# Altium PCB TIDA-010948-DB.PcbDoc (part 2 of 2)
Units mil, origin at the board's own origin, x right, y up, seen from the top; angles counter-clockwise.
Board outline 8000 x 3300 mil, 4 copper layers (Top Layer, Mid-Layer 1, Mid-Layer 2, Bottom Layer), stack 61.2 mil thick; 16 components, 34 nets, 141 pads, 139 vias.
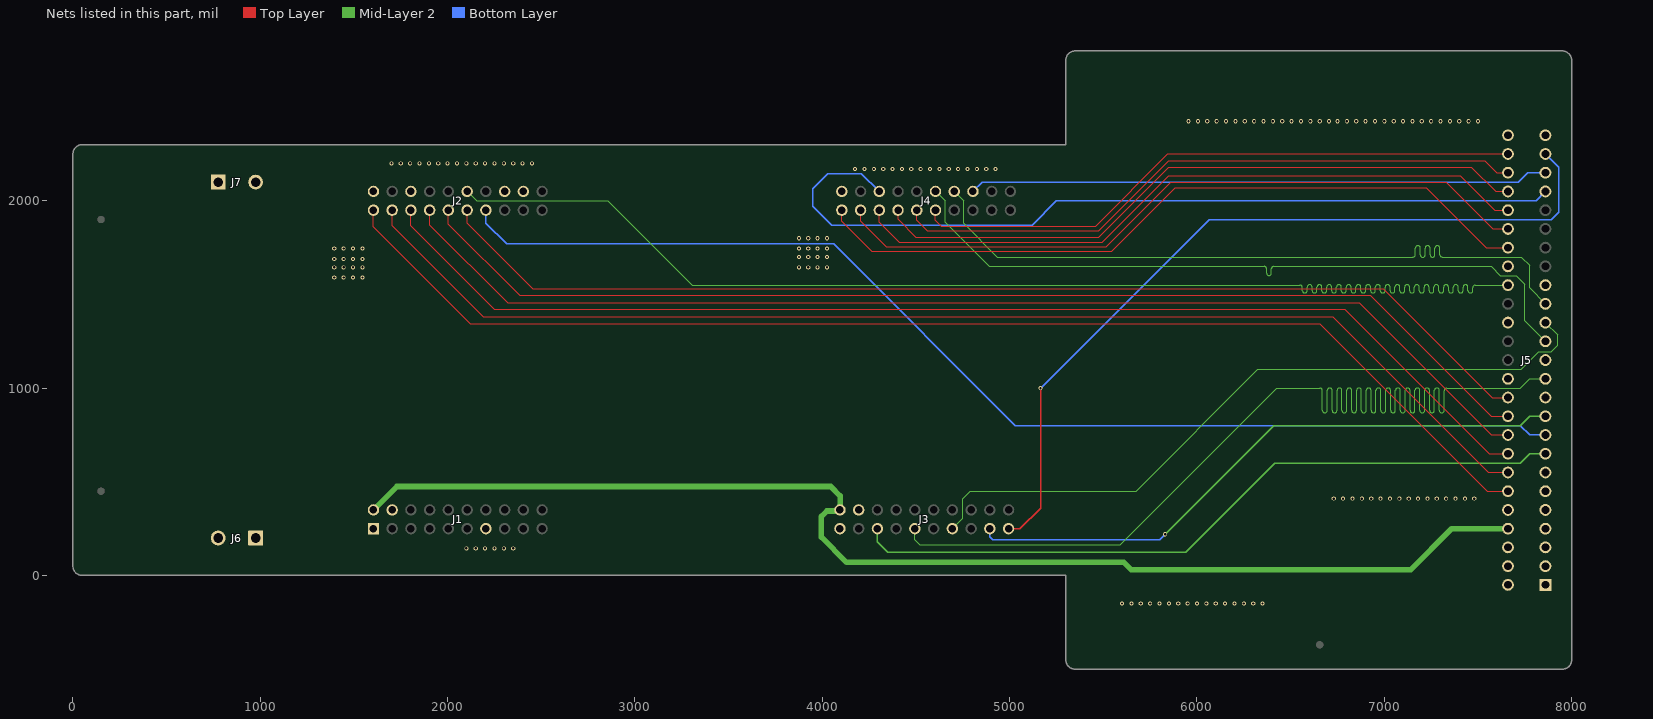
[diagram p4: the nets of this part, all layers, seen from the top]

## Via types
v1: diameter 22, hole 12, Top Layer to Bottom Layer, tented both sides, 136 vias
v2: diameter 200, hole 144, Top Layer to Bottom Layer, 2 vias
v3: diameter 22, hole 8, Top Layer to Bottom Layer, tented both sides, 1 vias

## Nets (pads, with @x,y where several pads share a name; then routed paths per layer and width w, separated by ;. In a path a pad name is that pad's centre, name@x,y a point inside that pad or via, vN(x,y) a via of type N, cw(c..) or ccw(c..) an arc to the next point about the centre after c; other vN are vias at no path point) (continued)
DOUT1_B2: J2.15 J5.51 | length 6942.2
  Mid-Layer 2 w6: J2.15@2104.18,2050 2154.18,2000 2855,2000 3305,1550 6520.53,1550 6549.53,1550 cw(c6549.53,1537) 6562.53,1537 6562.53,1521.18 ccw(c6575.53,1521.18) 6588.53,1521.18 6588.53,1539.22 cw(c6601.53,1539.22) 6614.53,1539.22 6614.53,1521.18 ccw(c6627.53,1521.18) 6640.53,1521.18 6640.53,1539.22 cw(c6653.53,1539.22) 6666.53,1539.22 6666.53,1521.18 ccw(c6679.53,1521.18) 6692.53,1521.18 6692.53,1539.22 cw(c6705.53,1539.22) 6718.53,1539.22 6718.53,1521.18 ccw(c6731.53,1521.18) 6744.53,1521.18 6744.53,1539.22 cw(c6757.53,1539.22) 6770.53,1539.22 6770.53,1521.18 ccw(c6783.53,1521.18) 6796.53,1521.18 6796.53,1539.22 cw(c6809.53,1539.22) 6822.53,1539.22 6822.53,1521.18 ccw(c6835.53,1521.18) 6848.53,1521.18 6848.53,1539.22 cw(c6861.53,1539.22) 6874.53,1539.22 6874.53,1521.18 ccw(c6887.53,1521.18) 6900.53,1521.18 6900.53,1539.22 cw(c6913.53,1539.22) 6926.53,1539.22 6926.53,1521.18 ccw(c6939.53,1521.18) 6952.53,1521.18 6952.53,1539.22 cw(c6965.53,1539.22) 6978.53,1539.22 6978.53,1521.18 ccw(c6991.53,1521.18) 7004.53,1521.18 7004.53,1539.22 cw(c7017.53,1539.22) 7030.53,1539.22 7030.53,1521.18 ccw(c7043.53,1521.18) 7056.53,1521.18 7056.53,1539.22 cw(c7069.53,1539.22) 7082.53,1539.22 7082.53,1521.18 ccw(c7095.53,1521.18) 7108.53,1521.18 7108.53,1539.22 cw(c7121.53,1539.22) 7134.53,1539.22 7134.53,1521.18 ccw(c7147.53,1521.18) 7160.53,1521.18 7160.53,1539.22 cw(c7173.53,1539.22) 7186.53,1539.22 7186.53,1521.18 ccw(c7199.53,1521.18) 7212.53,1521.18 7212.53,1539.22 cw(c7225.53,1539.22) 7238.53,1539.22 7238.53,1521.18 ccw(c7251.53,1521.18) 7264.53,1521.18 7264.53,1539.22 cw(c7277.53,1539.22) 7290.53,1539.22 7290.53,1521.18 ccw(c7303.53,1521.18) 7316.53,1521.18 7316.53,1539.22 cw(c7329.53,1539.22) 7342.53,1539.22 7342.53,1521.18 ccw(c7355.53,1521.18) 7368.53,1521.18 7368.53,1539.22 cw(c7381.53,1539.22) 7394.53,1539.22 7394.53,1521.18 ccw(c7407.53,1521.18) 7420.53,1521.18 7420.53,1539.22 cw(c7433.53,1539.22) 7446.53,1539.22 7446.53,1521.18 ccw(c7459.53,1521.18) 7472.53,1521.18 7472.53,1537 cw(c7485.53,1537) 7485.53,1550 7506.12,1550 J5.51@7660,1550
DOUT1_C1: J2.13
DOUT1_C2: J2.12
DRV_CS: J4.58 J5.64 | length 4547.6
  Bottom Layer w8: J4.58@4304.18,2050 4209.18,2145 4030,2145 3950,2065 3950,1970 4050,1870 5120,1870 5250,2000 7810,2000 J5.64@7860,2050
DRV_FAULT_1: J2.34 J5.25 | length 6193.4
  Bottom Layer w8: J2.34@2204.18,1950 2204.18,1880.82 2315,1770 4060,1770 5030,800 7725,800 7775,750 J5.25@7860,750
DRV_FAULT_2: J4.53 J5.67 | length 3097.2
  Bottom Layer w8: J4.53@4804.18,2050 4854.18,2100 7715,2100 7765,2150 J5.67@7860,2150
DRV_OFF1: J3.49 J5.28 | length 3295.9
  Top Layer w8: J3.49@4894.19,250 J3.49@4896.3,247.89
  Mid-Layer 2 w8: v1(5830,220) 6410,800 7725,800 7775,850 J5.28@7860,850
  Bottom Layer w8: J3.49@4896.3,247.89 J3.49@4894.19,250 4894.19,205.81 4910,190 5800,190 v1(5830,220)
DRV_OFF2: J3.50 J5.70 | length 4356.8
  Top Layer w8: J3.50@4994.19,250 5055,250 5165,360 v1(5165,1000)
  Bottom Layer w8: J3.50@4994.19,250 J3.50@4999.19,245 ; v1(5165,1000) 6065,1900 7890,1900 7930,1940 7930,2180 J5.70@7860,2250
DRV_SPI_CLK: J3.47 J5.43 | length 3844.7
  Mid-Layer 2 w6: J3.47@4694.19,250 4750,305.81 4750,410 4790,450 5675,450 6325,1100 7730,1100 7825,1195 7890,1195 7925,1230 7925,1285 J5.43@7860,1350
DRV_SPI_D0: J4.55 J5.40 | length 3844.1
  Mid-Layer 2 w6: J4.55@4604.18,2050 4605,2050 4655,2000 4655,1885 4890,1650 6329.42,1650 6358.42,1650 cw(c6358.42,1637) 6371.42,1637 6371.42,1614.16 ccw(c6384.42,1614.16) 6397.42,1614.16 6397.42,1637 cw(c6410.42,1637) 6410.42,1650 6475,1650 7570,1650 7620,1600 7705,1600 7750,1555 7750,1360 J5.40@7860,1250
DRV_SPI_D1: J4.54 J5.46 | length 3844.8
  Mid-Layer 2 w6: J4.54@4704.18,2050 4755,1999.18 4755,1880 4935,1700 7150,1700 7153,1700 ccw(c7153,1713) 7166,1713 7166,1747.29 cw(c7179,1747.29) 7192,1747.29 7192,1711.62 ccw(c7205,1711.62) 7218,1711.62 7218,1747.29 cw(c7231,1747.29) 7244,1747.29 7244,1711.62 ccw(c7257,1711.62) 7270,1711.62 7270,1747.29 cw(c7283,1747.29) 7296,1747.29 7296,1713 ccw(c7309,1713) 7309,1700 7355.03,1700 7730,1700 7775,1655 7775,1535 J5.46@7860,1450
DRV_SPI_MUX_S: J3.43 J5.22 | length 3875.6
  Mid-Layer 2 w8: J3.43@4294.19,250 4294.19,180.81 4350,125 5940,125 6415,600 7725,600 7775,650 J5.22@7860,650
GND: J1.22 J2.20 J3.62 J4.60 J5.7 J5.9 J5.15 J5.16 J5.19 J5.31 J5.36 J5.37 J5.45 J5.49 J5.54 J5.73 J5.75 J6.2 J7.2
  other v1: 5600,-150 5650,-150 5700,-150 5750,-150 5800,-150 5850,-150 5900,-150 5950,-150 6000,-150 6050,-150 6100,-150 6150,-150 6200,-150 6250,-150 6300,-150 6350,-150 2100,145 2150,145 2200,145 2250,145 2300,145 2350,145 6730,410 6780,410 6830,410 6880,410 6930,410 6980,410 7030,410 7080,410 7130,410 7180,410 7230,410 7280,410 7330,410 7380,410 7430,410 7480,410 1395,1590 1445,1590 1495,1590 1545,1590 1395,1645 1445,1645 1495,1645 1545,1645 3875,1645 3925,1645 3975,1645 4025,1645 1395,1690 1445,1690 1495,1690 1545,1690 3875,1700 3925,1700 3975,1700 4025,1700 1395,1745 1445,1745 1495,1745 1545,1745 3875,1745 3925,1745 3975,1745 4025,1745 3875,1800 3925,1800 3975,1800 4025,1800 4175,2170 4225,2170 4275,2170 4325,2170 4375,2170 4425,2170 4475,2170 4525,2170 4575,2170 4625,2170 4675,2170 4725,2170 4775,2170 4825,2170 4875,2170 4925,2170 1700,2200 1750,2200 1800,2200 1850,2200 1900,2200 1950,2200 2000,2200 2050,2200 2100,2200 2150,2200 2200,2200 2250,2200 2300,2200 2350,2200 2400,2200 2450,2200 5955,2425 6005,2425 6055,2425 6105,2425 6155,2425 6205,2425 6255,2425 6305,2425 6355,2425 6405,2425 6455,2425 6505,2425 6555,2425 6605,2425 6655,2425 6705,2425 6750,2425 6800,2425 6850,2425 6900,2425 6950,2425 7000,2425 7050,2425 7100,2425 7150,2425 7200,2425 7250,2425 7300,2425 7350,2425 7400,2425 7450,2425 7500,2425
PWM_A1_H: J2.40 J5.18 | length 6729.4
  Top Layer w6: J2.40@1604.18,1950 1604.18,1860.82 2120,1345 6655,1345 7550,450 J5.18@7660,450
PWM_A1_L: J2.39 J5.21 | length 6585
  Top Layer w6: J2.39@1704.18,1950 1704.18,1865.82 2190,1380 6725,1380 7555,550 J5.21@7660,550
PWM_A2_H: J4.77 J5.66 | length 3555.8
  Top Layer w6: J4.77@4405.51,1948.66 J4.77@4404.18,1950 4404.18,1900.82 4500,1805 5475,1805 5850,2180 7465,2180 7595,2050 J5.66@7660,2050
PWM_A2_L: J4.78 J5.63 | length 3687.5
  Top Layer w6: J4.78@4304.18,1950 4304.18,1885.82 4410,1780 5495,1780 5850,2135 7405,2135 7590,1950 J5.63@7660,1950
PWM_B1_H: J2.38 J5.24 | length 6443.6
  Top Layer w6: J2.38@1804.18,1950 1804.18,1865.82 2250,1420 6790,1420 7560,650 J5.24@7660,650
PWM_B1_L: J2.37 J5.27 | length 6299.3
  Top Layer w6: J2.37@1904.18,1950 1904.18,1870.82 2320,1455 6865,1455 7570,750 J5.27@7660,750
PWM_B2_H: J4.75 J5.72 | length 3282.2
  Top Layer w6: J4.75@4604.18,1950 4604.18,1895.82 4635,1865 5460,1865 5845,2250 J5.72@7660,2250
PWM_B2_L: J4.76 J5.69 | length 3417.5
  Top Layer w6: J4.76@4504.18,1950 4504.18,1895.82 4560,1840 5475,1840 5850,2215 7535,2215 7600,2150 J5.69@7660,2150 J5.69@7658.5,2151.5
PWM_C1_H: J2.36 J5.30 | length 6154.9
  Top Layer w6: J2.36@2004.18,1950 2004.18,1875.82 2385,1495 6925,1495 7570,850 J5.30@7660,850
PWM_C1_L: J2.35 J5.33 | length 6010.6
  Top Layer w6: J2.35@2104.18,1950 2104.18,1880.82 2455,1530 6995,1530 7575,950 J5.33@7660,950
PWM_C2_H: J4.79 J5.60 | length 3817.7
  Top Layer w6: J4.79@4204.18,1950 4204.18,1890.82 4340,1755 5515,1755 5860,2100 7330,2100 7580,1850 J5.60@7660,1850
PWM_C2_L: J4.80 J5.57 | length 3955
  Top Layer w6: J4.80@4104.18,1950 4104.18,1890.82 4265,1730 5545,1730 5885,2070 7225,2070 7545,1750 J5.57@7660,1750
SDFM_CLK_IN: J1.7
SDFM_CLK_SHIFT: J2.18
SDFM_CLK_SOURCE_BUF: J3.45 J5.34 | length 6948.4
  Mid-Layer 2 w6: J3.45@4494.19,250 4494.19,190.81 4520,165 5590,165 6425,1000 6634.54,1000 6656.45,1000 cw(c6656.45,987) 6669.45,987 6669.45,881.38 ccw(c6682.45,881.38) 6695.45,881.38 6695.45,987.59 cw(c6708.45,987.59) 6721.45,987.59 6721.45,881.38 ccw(c6734.45,881.38) 6747.45,881.38 6747.45,987.59 cw(c6760.45,987.59) 6773.45,987.59 6773.45,881.38 ccw(c6786.45,881.38) 6799.45,881.38 6799.45,987.59 cw(c6812.45,987.59) 6825.45,987.59 6825.45,881.38 ccw(c6838.45,881.38) 6851.45,881.38 6851.45,987.59 cw(c6864.45,987.59) 6877.45,987.59 6877.45,881.38 ccw(c6890.45,881.38) 6903.45,881.38 6903.45,987.59 cw(c6916.45,987.59) 6929.45,987.59 6929.45,881.38 ccw(c6942.45,881.38) 6955.45,881.38 6955.45,987.59 cw(c6968.45,987.59) 6981.45,987.59 6981.45,881.38 ccw(c6994.45,881.38) 7007.45,881.38 7007.45,987.59 cw(c7020.45,987.59) 7033.45,987.59 7033.45,881.38 ccw(c7046.45,881.38) 7059.45,881.38 7059.45,987.59 cw(c7072.45,987.59) 7085.45,987.59 7085.45,881.38 ccw(c7098.45,881.38) 7111.45,881.38 7111.45,987.59 cw(c7124.45,987.59) 7137.45,987.59 7137.45,881.38 ccw(c7150.45,881.38) 7163.45,881.38 7163.45,987.59 cw(c7176.45,987.59) 7189.45,987.59 7189.45,881.38 ccw(c7202.45,881.38) 7215.45,881.38 7215.45,987.59 cw(c7228.45,987.59) 7241.45,987.59 7241.45,881.38 ccw(c7254.45,881.38) 7267.45,881.38 7267.45,987.59 cw(c7280.45,987.59) 7293.45,987.59 7293.45,881.38 ccw(c7306.45,881.38) 7319.45,881.38 7319.45,987 cw(c7332.45,987) 7332.45,1000 7335.45,1000 7725,1000 7775,1050 J5.34@7860,1050
VBus: J5.1 J5.3 J5.4 J5.6 J6.1 J7.1
VSYS_3V3: J1.1 J3.41 J5.10 J5.13
VSYS_5V0: J1.21 J3.61 J5.12 | length 6690.9
  Mid-Layer 2 w30: J1.21@1604.18,350 1729.18,475 4045,475 4095,425 4095,350.81 J3.61@4094.19,350 4088.25,344.06 4024.06,344.06 3995,315 3995,205 4130,70 5610,70 5650,30 7140,30 7360,250 J5.12@7660,250
pads on no net: FID1.1 FID2.1 FID3.1 FID4.1 FID5.1 FID6.1 J1.2 J1.3 J1.4 J1.5 J1.6 J1.8 J1.9 J1.10 J1.23 J1.24 J1.25 J1.26 J1.27 J1.28 J1.29 J1.30 J2.11 J2.14 J2.16 J2.17 J2.31 J2.33 J3.42 J3.46 J3.48 J3.63 J3.64 J3.65 J3.66 J3.67 J3.68 J3.69 J3.70 J4.51 J4.52 J4.56 J4.57 J4.59 J4.71 J4.72 J4.73 J4.74 J5.52 J5.55 J5.58 J5.61 LBL1.0
copper on no net:
  other v2: 154.17,150 154.17,2150

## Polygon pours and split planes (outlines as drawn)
VBus on Bottom Layer "VBUS_L04_P012" (solid, pour order 12): 1075,500 1065,490 1065,500
VBus on Bottom Layer " " (solid, pour order 0): 7905,-125 6425,-125 5800,500 1065,500 1065,75 675,75 650,100 650,2200 675,2225 850,2225 875,2200 875,675 925,625 5905,625 6480,50 7525,50 7580,105 7895,105 7950,50 7950,-80
GND on Bottom Layer "GND_L04_P006" (solid, pour order 6): 650,2200 700,2250 5300,2250 5575,2525 7875,2525 7950,2450 7950,-80 7830,-200 5575,-200 5375,0 5300,75 730,75 650,155
GND on Mid-Layer 1 "GND_L02_P008" (solid, pour order 8): 645,2195 695,2245 5295,2245 5570,2520 7870,2520 7965,2425 7965,-65 7825,-205 5570,-205 5370,-5 5295,70 725,70 645,150
VSYS_3V3 on Mid-Layer 1 "VSYS_3V3_L02_P003" (solid, pour order 3): 7915,95 7895,75 7475,75 1550,75 1475,150 1475,250 1525,300 7690,300 7790,400 7900,400 7915,385
GND on Top Layer "GND_L01_P001" (solid, pour order 1): 645,2195 695,2245 5295,2245 5570,2520 7870,2520 7945,2445 7945,-85 7825,-205 5570,-205 5370,-5 5295,70 725,70 645,150
GND on Mid-Layer 2 "GND_L03_P009" (solid, pour order 9): 645,2195 695,2245 5295,2245 5570,2520 7870,2520 7945,2445 7945,-85 7825,-205 5570,-205 5370,-5 5295,70 725,70 645,150

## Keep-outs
Keep-Out Layer:
  lines w10: 4550,2905 cw(c4550,2900) 4555,2900 ccw(c4550,2900) 4550,2905
  text ".Layer_Name" at 177,-1408.49 h60

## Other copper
Top Layer:
  text ".Layer_Name" at 177,-1408.49 h60
Mid-Layer 1:
Bottom Layer:
  pour cut-out: 1075.2,489.8 1100.2,489.8 1075.2,464.8
  pour cut-out: 1075.2,75 1075.2,100 1100.2,75
  pour cut-out: 1065,75 1040,75 1065,100
  text ".Layer_Name" at 177,-1408.49 h60

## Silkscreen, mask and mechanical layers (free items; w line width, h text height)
Top Overlay:
  text "3V3" at 1630,35 h35 r90
  text ".Layer_Name" at 177,-1408.49 h60
Bottom Overlay:
  text "GND" at 1618,2228 h40 r90
  text "VBUS" at 790,1820 h35 r90
  text "GND" at 1010,1820 h35 r90
  text "TIDA-010948" at 3758.98,885 h60
  text "Rev.E1" at 3085,875.81 h80
  text "TI" at 2454,875 h60
  text ".CopyrightYear" at 2730,875 h60
  text "©" at 2830,870 h105
  text "GND" at 795,640 h35 r90
  text "VBUS" at 995,640 h35 r90
  text ".Layer_Name" at 177,-1408.49 h60
Top Paste:
  text ".Layer_Name" at 177,-1408.49 h60
Bottom Paste:
  text ".Layer_Name" at 177,-1408.49 h60
Top Solder:
  text ".Layer_Name" at 177,-1408.49 h60
  text ".Layer_Name" at 177,-1408.49 h60
Bottom Solder:
  text ".Layer_Name" at 177,-1408.49 h60
Drill Guide:
  text ".Layer_Name" at 177,-1408.49 h60
M1 Board Outline:
  the board outline again, w10
  text ".Layer_Name" at 177,-1408.49 h60
M2 Board Dimensions:
  rectangle: -400,-825 -275,-700
  rectangle: -275,-950 100,-825
  lines w7: -400,-825 600,-825 ; -275,-950 -275,-700 ; -150,-950 -150,-700 ; 100,-950 100,-700 ; 350,-950 350,-700 ; -400,-950 600,-950 600,-700 -400,-700 -400,-950
  text ".Layer_Name" at 177,-1408.49 h60
M3 3D STEP Top:
  text ".Layer_Name" at 177,-1408.49 h60
M4 3D STEP Bottom:
  text ".Layer_Name" at 177,-1408.49 h60
M5 Assembly Top:
  lines w10: -692,-1480.17 5908,-1480.17 ; -692,-1276.83 5910,-1276.83 ; -692,-1073.5 -692,-1683.5 3313,-1683.5 5910,-1683.5 5910,-1073.5 -691.5,-1073.5 -691.5,-1683.5 884,-1683.5 ; 1773,-1683.5 1773,-1073.5 ; 3040,-1276.83 3040,-1073.5 ; 3880,-1276.83 3880,-1073.5 ; 4502,-1690 4502,-1487.17
  text "COMPONENTS MARKED 'DNP' SHOULD NOT BE POPULATED." at 753.5,-868.5 h60
  text "ASSEMBLY VARIANT:" at 753,-984 h60
  text ".VariantName" at 1789,-984 h60
  text "PCB VIEWED FROM TOP SIDE" at -628.5,-1205.67 h60
  text "BOARD #:" at 1848,-1205.67 h60
  text ".PRJ_Number" at 2393.5,-1205.67 h60
  text "REV:" at 3238,-1205.67 h60
  text ".PCB_Rev" at 3529.5,-1205.67 h60
  text "SVN REV:" at 4076,-1205.67 h60
  text ".VersionControl_RevNumber" at 4582,-1205.67 h60
  text "PLOT NAME =" at -628.5,-1614.34 h60
  text ".plot_File_Name" at 177,-1614.34 h60
  text "GENERATED    :" at 1850,-1614.34 h60
  text ".Print_Date" at 2719.5,-1614.34 h60
  text ".Print_Time" at 3448.5,-1614.34 h60
  text "TEXAS INSTRUMENTS" at 4713,-1614.34 h60
M6 Assembly Bottom:
  lines w10: -692.5,-1277.33 5909.5,-1277.33 ; -690.5,-1480.67 5909.5,-1480.67 ; 715.5,-1690.5 715.5,-1487.67 ; 1337.5,-1277.33 1337.5,-1074 ; 2177.5,-1277.33 2177.5,-1074 ; 3444.5,-1684 3444.5,-1074 ; 4333.5,-1684 5909,-1684 5909,-1074 -692.5,-1074 -692.5,-1684 1904.5,-1684 5909.5,-1684 5909.5,-1074
  text "COMPONENTS MARKED 'DNP' SHOULD NOT BE POPULATED." at 5702,-868 h60
  text ".VariantName" at 4658,-984 h60
  text "ASSEMBLY VARIANT:" at 5697,-984 h60
  text ".VersionControl_RevNumber" at 635.5,-1206.17 h60
  text "SVN REV:" at 1141.5,-1206.17 h60
  text ".PCB_Rev" at 1688,-1206.17 h60
  text "REV:" at 1979.5,-1206.17 h60
  text ".PRJ_Number" at 2824,-1206.17 h60
  text "BOARD #:" at 3369.5,-1206.17 h60
  text "PCB VIEWED FROM BOTTOM SIDE" at 5846,-1206.17 h60
  text "TEXAS INSTRUMENTS" at 504.5,-1614.84 h60
  text ".Print_Time" at 1769,-1614.84 h60
  text ".Print_Date" at 2498,-1614.84 h60
  text "GENERATED    :" at 3367.5,-1614.84 h60
  text ".plot_File_Name" at 5040.5,-1614.84 h60
  text "PLOT NAME =" at 5846,-1614.84 h60
M9 Title Sheet:
  drawing of 57 lines, arcs and shapes, not listed
  text "1" at 339.84,7486.5 h70
  text "2" at 2835.5,7486.5 h70
  text "3" at 5324.84,7486.5 h70
  text "4" at 7831.51,7486.5 h70
  text "5" at 10330.5,7486.5 h70
  text "6" at 12835.5,7486.5 h70
  text "A" at -816.5,6343.5 h70
  text "A" at 13983.5,6343.5 h70
  text "B" at -816.5,3963.5 h70
  text "B" at 13983.5,3963.5 h70
  text "C" at -816.5,1588.5 h70
  text "C" at 13983.5,1588.5 h70
  text "PROJECT TITLE:" at 10943.5,-272.5 h45
  text ".PRJ_Title" at 10993.5,-405.83 h70
  text "DESIGNED FOR:" at 10943.5,-573.5 h45
  text ".PRJ_Customer" at 10993.5,-713.5 h70
  text "D" at -816.5,-781.5 h70
  text "D" at 13983.5,-781.5 h70
  text "FILE NAME:" at 10943.5,-873.5 h45
  text ".PCB_File_Name_No_Path" at 10993.5,-993.5 h70
  text "Texas Instruments (TI) and/or its licensors do not warrant the accuracy or completeness of this specification" at 5974,-1155.34 h45
  text "ENGINEER:" at 10943.5,-1163.5 h45
  text "LAYOUT BY:" at 12448.5,-1163.5 h45
  text "or any information contained therein. TI and/or its licensors do not warrant that this design will meet" at 5929.01,-1268 h45
  text ".PRJ_Engineer" at 10993.5,-1318.49 h70
  text ".PCB_Layout" at 12499,-1318.49 h70
  text "the specifications, will be suitable for your application or fit for any particular purpose, or will operate in" at 5929.01,-1380.67 h45
  text ".Layer_Name" at 177,-1408.49 h60
  text "ALTIUM DESIGNER VERSION:" at 12448.5,-1473.5 h45
  text "an implementation. TI and/or its licensors do not warrant that the design is production worthy. You should" at 5929.01,-1493.33 h45
  text "completely validate and test your design implementation to confirm the system functionality for your application." at 5974,-1606 h45
  text ".print_Scale" at 10993.5,-1606.83 h70
  text ".Application_BuildNumber" at 12499,-1606.83 h70
  text "1" at 339.84,-1813.5 h70
  text "2" at 2835.5,-1813.5 h70
  text "3" at 5324.84,-1813.5 h70
  text "4" at 7831.51,-1813.5 h70
  text "5" at 10330.5,-1813.5 h70
  text "6" at 12835.5,-1813.5 h70
M10 Fab Notes:
  drawing of 185 lines, arcs and shapes, not listed
  text "DESIGN INFORMATION" at 11981.02,5360 h60
  text "MIN. TRACK WIDTH:" at 11336.46,5180 h60
  text "8" at 12432.7,5180 h60
  text "MIL" at 12587.46,5180 h60
  text "MIN. CLEARANCE:" at 11336.46,5048 h60
  text "0.2" at 12372.7,5048 h60
  text "mm" at 12587.46,5048 h60
  text "MIN. VIA PAD SIZE:" at 11336.46,4916 h60
  text "24" at 12402.71,4916 h60
  text "MIL" at 12587.46,4916 h60
  text "0.05mm (2MIL)" at 12031.46,4774.29 h60
  text "MINIMUM ANNULAR RING" at 11007.23,4770 h60
  text "EXTERNAL" at 12739.46,4770 h60
  text "PER" at 11207.23,4652 h60
  text "IPC-D-275 CLASS 2 LEVEL C" at 11427.23,4652 h60
  text "MIL, HOLES" at 12915.46,4539.71 h60
  text "+/-" at 12523,4539 h60
  text "+/-" at 13377,4539 h60
  text "REGISTRATION TOLERANCES:" at 11007.23,4534 h60
  text "METAL" at 12207,4534 h60
  text "5" at 12783.2,4534 h60
  text "3" at 13616.2,4534 h60
  text "MIL" at 13732.46,4534 h60
  text "MATERIAL:" at 10932.46,4324.54 h60
  text "FR-4 High Tg" at 11918.9,4184.21 h60
  text "FR-408" at 11353.46,4175.64 h60
  text "X" at 11765.46,4175.64 h60
  text "OTHER" at 12841.46,4175.64 h60
  text "62 MIL (1.6mm) +/-10%" at 11673.56,4012.92 h60
  text "THICKNESS:" at 11007.23,4008.64 h60
  text "X" at 11545.4,4008.64 h60
  text "OTHER" at 12958.46,4008.64 h60
  text "TOLERANCE:" at 11007.23,3850.64 h60
  text "X" at 11846.53,3850.64 h60
  text "ANSI IPC-6012 TYPE 3 CLASS 2" at 12033.48,3850.64 h60
  text "OTHER +/-" at 12033.46,3694.64 h60
  text "BOW & TWIST:" at 11007.23,3537.64 h60
  text "X" at 11846.53,3537.64 h60
  text "ANSI IPC-6012 TYPE 3 CLASS 2" at 12033.48,3537.64 h60
  text "OTHER +/-" at 12033.46,3379.13 h60
  text "DRILLING:" at 10932.46,3240.64 h60
  text "REFERENCE:" at 11007.23,3123.64 h60
  text "X" at 11655.46,3123.64 h60
  text "AS SHOWN" at 11842.46,3123.64 h60
  text "X" at 12556.46,3123.64 h60
  text "NC_DRILL FILES" at 12693.46,3123.64 h60
  text "PTH MIN COPPER THICKNESS:" at 11007.23,2965.64 h60
  text "X" at 12357.46,2965.64 h60
  text "1MIL" at 12494.46,2965.64 h60
  text "OTHER" at 12991.46,2965.64 h60
  text "BOARD FINISH:" at 10932.46,2806.64 h60
  text "SILKSCREEN:" at 11087.68,2688.64 h60
  text "X" at 12036.46,2688.64 h60
  text "TOP" at 12162.46,2688.64 h60
  text "X" at 12546.46,2688.64 h60
  text "BOTTOM" at 12673.46,2688.64 h60
  text "SILKSCREEN COLOR:" at 11087.68,2521.64 h60
  text "X" at 12035.42,2521.64 h60
  text "WHITE" at 12162.46,2521.64 h60
  text "OTHER" at 12673.46,2521.64 h60
  text "SOLDER RESIST COLOR:" at 11087.68,2351.64 h60
  text "X" at 11655.42,2192.44 h60
  text "GREEN" at 11782.46,2192.44 h60
  text "BLUE" at 12373.46,2192.44 h60
  text "OTHER" at 12911.46,2192.44 h60
  text "IMMERSION GOLD (ENIG)" at 11993.46,2003.92 h60
  text "ENEPIG" at 13331,2000.64 h60
  text "SURFACE FINISH:" at 10932.46,1999.64 h60
  text "X" at 11806.51,1999.64 h60
  text "IMM. TIN/SILVER OR EQUIV" at 11262,1842.64 h60
  text "OTHER" at 12693.46,1842.64 h60
  text "ARRAY/PANEL:" at 10932.46,1663.64 h60
  text "CUT AND TRIM PER MECH LAYER 1" at 11993.46,1659.35 h60
  text "N.C. ROUTE" at 11993.46,1507.64 h60
  text "X" at 12672.46,1507.64 h60
  text "V. SCORE" at 12859.46,1507.64 h60
  text "CERTIFICATION:" at 10932.46,1370.64 h60
  text "MATERIALS AND WORKMANSHIP FOR ALL PCBS" at 11657.46,1370.64 h60
  text "TO MEET OR EXCEED THE REQUIREMENTS OF:" at 11657.46,1272.64 h60
  text "X" at 11283.96,1136.13 h60
  text "ANSI IPC-A-600F CLASS ->" at 11422.96,1136.13 h60
  text "X" at 13062.02,1136.13 h60
  text "2" at 13180.96,1136.14 h60
  text "1" at 12865.96,1134.64 h60
  text "3" at 13534.96,1134.64 h60
  text "X" at 11286.02,976.64 h60
  text "UL 94V-0" at 11422.96,976.64 h60
  text "X" at 12098.02,976.64 h60
  text "RoHS" at 12234.96,976.64 h60
  text "OTHER" at 12879.36,976.64 h60
  text "PER ORDER" at 13276.42,976.64 h60
  text "ADDITIONAL REQUIREMENTS:" at 10932.46,835.64 h60
  text "MICROSECTION:" at 11007.23,720.64 h60
  text "YES" at 11912.96,720.64 h60
  text "REQUIRED" at 12774.46,564.49 h60
  text "BARE BOARD ELEC. TEST:" at 11007.23,561.64 h60
  text "NONE" at 12312.96,561.64 h60
  text "X" at 12647.46,561.64 h60
  text "PER ORDER" at 13366.46,561.64 h60
  text "MANUFACTURER'S UL:" at 11007.23,404.64 h60
  text "RAIL" at 12172.96,400.35 h60
  text "METAL" at 12664.77,400.35 h60
  text "X" at 13040,400 h60
  text "SILK" at 13176.46,400.35 h60
  text ".Layer_Name" at 177,-1408.49 h60
M11 Gerber Information:
  lines w10: -692,-1480.17 5908,-1480.17 ; -692,-1276.83 5910,-1276.83 ; -692,-1073.5 -692,-1683.5 3313,-1683.5 5910,-1683.5 5910,-1073.5 -691.5,-1073.5 -691.5,-1683.5 884,-1683.5 ; 1773,-1683.5 1773,-1073.5 ; 3040,-1276.83 3040,-1073.5 ; 3880,-1276.83 3880,-1073.5 ; 4502,-1690 4502,-1487.17
  text "ALL ARTWORK VIEWED FROM TOP SIDE" at -628.5,-1205.67 h60
  text "BOARD #:" at 1848,-1205.67 h60
  text ".PRJ_Number" at 2393.5,-1205.67 h60
  text "REV:" at 3238,-1205.67 h60
  text ".PCB_Rev" at 3529.5,-1205.67 h60
  text "SVN REV:" at 4076,-1205.67 h60
  text ".VersionControl_RevNumber" at 4582,-1205.67 h60
  text "LAYER NAME =" at -628.5,-1408.49 h60
  text "PLOT NAME =" at -628.5,-1614.34 h60
  text ".plot_File_Name" at 177,-1614.34 h60
  text "GENERATED    :" at 1850,-1614.34 h60
  text ".Print_Date" at 2719.5,-1614.34 h60
  text ".Print_Time" at 3448.5,-1614.34 h60
  text "TEXAS INSTRUMENTS" at 4713,-1614.34 h60
M12 Stackup:
  drawing of 527 lines, arcs and shapes, not listed
  text "Layer" at 9408.08,7737.5 h60
  text "Name" at 9817.99,7737.5 h60
  text "Material" at 10747.73,7737.5 h60
  text "Thickness" at 11607.5,7737.5 h60
  text "Constant" at 12257.34,7737.5 h60
  text "Board Layer Stack" at 12827.2,7737.5 h60
  text "Board Layer Stack" at 13946.88,7737.5 h60
  text "Top Overlay" at 9817.99,7617.5 h60
  text "Top Solder" at 9817.99,7497.5 h60
  text "Solder Resist" at 10747.73,7497.5 h60
  text "0.40mil" at 11607.5,7497.5 h60
  text "3.5" at 12257.34,7497.5 h60
  text "1" at 9408.08,7377.5 h60
  text "Top Layer" at 9817.99,7377.5 h60
  text "1.40mil" at 11607.5,7377.5 h60
  text "Dielectric1" at 9817.99,7257.5 h60
  text "FR-4" at 10747.73,7257.5 h60
  text "10.00mil" at 11607.5,7257.5 h60
  text "4.2" at 12257.34,7257.5 h60
  text "2" at 9408.08,7137.5 h60
  text "Mid-Layer 1" at 9817.99,7137.5 h60
  text "1.42mil" at 11607.5,7137.5 h60
  text "Dielectric2" at 9817.99,7017.5 h60
  text "FR-4" at 10747.73,7017.5 h60
  text "35.57mil" at 11607.5,7017.5 h60
  text "4.2" at 12257.34,7017.5 h60
  text "3" at 9408.08,6897.5 h60
  text "Mid-Layer 2" at 9817.99,6897.5 h60
  text "1.42mil" at 11607.5,6897.5 h60
  text "Dielectric 3" at 9817.99,6777.5 h60
  text "FR-4" at 10747.73,6777.5 h60
  text "10.00mil" at 11607.5,6777.5 h60
  text "4.2" at 12257.34,6777.5 h60
  text "4" at 9408.08,6657.5 h60
  text "Bottom Layer" at 9817.99,6657.5 h60
  text "1.40mil" at 11607.5,6657.5 h60
  text "Bottom Solder" at 9817.99,6537.5 h60
  text "Solder Resist" at 10747.73,6537.5 h60
  text "0.40mil" at 11607.5,6537.5 h60
  text "3.5" at 12257.34,6537.5 h60
  text "Bottom Overlay" at 9817.99,6417.5 h60
  text ".Layer_Name" at 177,-1408.49 h60
M13 Component Bodies Top:
  text ".Layer_Name" at 177,-1408.49 h60
M14 Component Bodies Bottom:
  text ".Layer_Name" at 177,-1408.49 h60
M15 Courtyards Top:
  text ".Layer_Name" at 177,-1408.49 h60
M16 Courtyards Bottom:
  text ".Layer_Name" at 177,-1408.49 h60
Drill Drawing:
  circle w10: c5163.72,2201.9 r27.63
  lines w10: 5136.09,2298.6 5191.34,2298.6 5191.34,2353.85 5136.09,2353.85 5136.09,2298.6 ; 5136.09,2450.54 5163.72,2422.92 5191.34,2450.54 5163.72,2478.17 5136.09,2450.54 ; 5136.09,2547.24 5191.34,2547.24 5191.34,2602.49 5136.09,2602.49 5136.09,2547.24 ; 5136.09,2726.81 5191.34,2726.81 5163.72,2671.56 5136.09,2726.81 ; 5136.09,2809.69 5149.9,2809.69 5163.72,2795.88 5177.53,2809.69 5191.34,2809.69 5177.53,2823.5 5191.34,2837.32 5177.53,2837.32 5163.72,2851.13 5149.9,2837.32 5136.09,2837.32 5149.9,2823.5 5136.09,2809.69 ; 5147.14,2309.65 5180.29,2309.65 5180.29,2342.8 5147.14,2342.8 5147.14,2309.65
  lines w12: 5086,2136.98 7064.02,2136.98 ; 5086,2882.9 7064.02,2882.9 ; 5423.86,2012.66 5423.86,3007.22 ; 5755.86,2012.66 5755.86,3007.22 ; 6392.43,2012.66 6392.43,3007.22 ; 6651.57,2012.66 6651.57,3007.22 ; 5086,2012.66 7064.02,2012.66 7064.02,3007.22 5086,3007.22 5086,2012.66
  text "Symbol" at 5160.59,2920.2 h72
  text "Quantity" at 5461.16,2920.2 h72
  text "Finished Hole Size" at 5793.16,2920.2 h72
  text "Plated" at 6429.72,2920.2 h72
  text "Hole Type" at 6688.86,2920.2 h72
  text "1" at 5461.16,2795.88 h60
  text "8.00mil (0.203mm)" at 5793.16,2795.88 h60
  text "PTH" at 6429.72,2795.88 h60
  text "Round" at 6688.86,2795.88 h60
  text "136" at 5461.16,2671.56 h60
  text "12.00mil (0.305mm)" at 5793.16,2671.56 h60
  text "PTH" at 6429.72,2671.56 h60
  text "Round" at 6688.86,2671.56 h60
  text "80" at 5461.16,2547.24 h60
  text "40.16mil (1.020mm)" at 5793.16,2547.24 h60
  text "PTH" at 6429.72,2547.24 h60
  text "Round" at 6688.86,2547.24 h60
  text "50" at 5461.16,2422.92 h60
  text "40.95mil (1.040mm)" at 5793.16,2422.92 h60
  text "PTH" at 6429.72,2422.92 h60
  text "Round" at 6688.86,2422.92 h60
  text "4" at 5461.16,2298.6 h60
  text "51.18mil (1.300mm)" at 5793.16,2298.6 h60
  text "PTH" at 6429.72,2298.6 h60
  text "Round" at 6688.86,2298.6 h60
  text "2" at 5461.16,2174.28 h60
  text "144.00mil (3.658mm)" at 5793.16,2174.28 h60
  text "PTH" at 6429.72,2174.28 h60
  text "Round" at 6688.86,2174.28 h60
  text "273 Total" at 5461.16,2049.96 h60
  text ".Layer_Name" at 177,-1408.49 h60

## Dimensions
5300,2300 to 5350.09,2800 on M2 Board Dimensions
8000,2800 to 5300,2800 on M2 Board Dimensions
8000,2800 to 8000,-500 on M2 Board Dimensions
8000,-500 to 0,-135 on M2 Board Dimensions
0,0 to 50,2300 on M2 Board Dimensions
-400,-950 to 600,-950 on M2 Board Dimensions
5300,0 to 0,0 on M2 Board Dimensions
